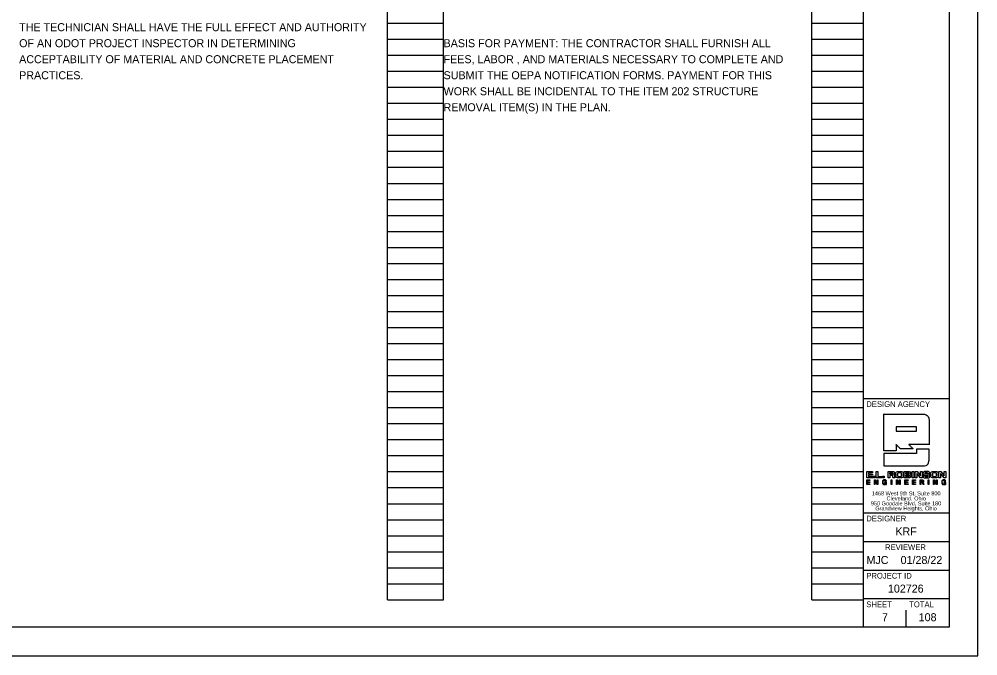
# Model space of a CAD drawing. Extents: x 0 to 34, y 0 to 22.
# Drawn here: x 17.24 to 34, y 0 to 11.13 of the extents above; entities that cross this region are included whole.
import ezdxf

# ---------------------------------------------------------------- set-up
doc = ezdxf.new("R2010")
doc.units = 0
for name, color, linetype in [('SH_Border', 7, 'Continuous'), ('SH_Cut_Line', 7, 'Continuous'), ('SH_Data', 7, 'Continuous'), ('SH_Text', 7, 'Continuous')]:
    doc.layers.add(name, color=color, linetype=linetype)

msp = doc.modelspace()

# ---------------------------------------------------------------- linework, layer by layer
at = {"layer": 'SH_Border'}
for p, q in [((32, 0.5), (32, 21.5)), ((32, 4.5), (33.5, 4.5)), ((32, 2.5), (33.5, 2.5)), ((32, 2), (33.5, 2)), ((32, 1.5), (33.5, 1.5)), ((32, 1), (33.5, 1))]:
    msp.add_line(p, q, dxfattribs=at)
msp.add_lwpolyline([(1.5, 21.5), (33.5, 21.5), (33.5, 0.5), (1.5, 0.5)], close=True, dxfattribs=at)
at = {"layer": 'SH_Cut_Line'}
msp.add_lwpolyline([(0, 0), (34, 0), (34, 22), (0, 22)], close=True, dxfattribs=at)
at = {"layer": 'SH_Data'}
for p, q in [((23.68, 0.98), (23.68, 21.14)), ((24.66, 0.98), (24.66, 21.14)), ((31.1, 0.98), (31.1, 21.14)), ((32, 0.98), (32, 21.14)), ((23.68, 11.06), (24.66, 11.06)), ((31.1, 11.06), (32, 11.06)), ((23.68, 10.78), (24.66, 10.78)), ((31.1, 10.78), (32, 10.78)), ((23.68, 10.5), (24.66, 10.5)), ((31.1, 10.5), (32, 10.5)), ((23.68, 10.22), (24.66, 10.22)), ((31.1, 10.22), (32, 10.22)), ((23.68, 9.94), (24.66, 9.94)), ((31.1, 9.94), (32, 9.94)), ((23.68, 9.66), (24.66, 9.66)), ((31.1, 9.66), (32, 9.66)), ((23.68, 9.38), (24.66, 9.38)), ((31.1, 9.38), (32, 9.38)), ((23.68, 9.1), (24.66, 9.1)), ((31.1, 9.1), (32, 9.1)), ((23.68, 8.82), (24.66, 8.82)), ((31.1, 8.82), (32, 8.82)), ((23.68, 8.54), (24.66, 8.54)), ((31.1, 8.54), (32, 8.54)), ((23.68, 8.26), (24.66, 8.26)), ((31.1, 8.26), (32, 8.26)), ((23.68, 7.98), (24.66, 7.98)), ((31.1, 7.98), (32, 7.98)), ((23.68, 7.7), (24.66, 7.7)), ((31.1, 7.7), (32, 7.7)), ((23.68, 7.42), (24.66, 7.42)), ((31.1, 7.42), (32, 7.42)), ((23.68, 7.14), (24.66, 7.14)), ((31.1, 7.14), (32, 7.14)), ((23.68, 6.86), (24.66, 6.86)), ((31.1, 6.86), (32, 6.86)), ((23.68, 6.58), (24.66, 6.58)), ((31.1, 6.58), (32, 6.58)), ((23.68, 6.3), (24.66, 6.3)), ((31.1, 6.3), (32, 6.3)), ((23.68, 6.02), (24.66, 6.02)), ((31.1, 6.02), (32, 6.02)), ((23.68, 5.74), (24.66, 5.74)), ((31.1, 5.74), (32, 5.74)), ((23.68, 5.46), (24.66, 5.46)), ((31.1, 5.46), (32, 5.46)), ((23.68, 5.18), (24.66, 5.18)), ((31.1, 5.18), (32, 5.18)), ((23.68, 4.9), (24.66, 4.9)), ((31.1, 4.9), (32, 4.9)), ((23.68, 4.62), (24.66, 4.62)), ((31.1, 4.62), (32, 4.62)), ((23.68, 4.34), (24.66, 4.34)), ((31.1, 4.34), (32, 4.34)), ((23.68, 4.06), (24.66, 4.06)), ((31.1, 4.06), (32, 4.06)), ((32.929, 4.003), (32.574, 4.003)), ((32.574, 4.003), (32.574, 3.925)), ((32.574, 3.925), (32.929, 3.925)), ((32.929, 3.925), (32.929, 4.003)), ((23.68, 3.78), (24.66, 3.78)), ((31.1, 3.78), (32, 3.78)), ((23.68, 3.5), (24.66, 3.5)), ((31.1, 3.5), (32, 3.5)), ((32.75, 3.5), (32.75, 3.5)), ((23.68, 3.22), (24.66, 3.22)), ((31.1, 3.22), (32, 3.22)), ((32.463, 3.201), (32.463, 3.173)), ((32.743, 3.202), (32.743, 3.178)), ((32.743, 3.159), (32.743, 3.133)), ((33.001, 3.066), (33.001, 3.039)), ((33.001, 3.039), (33.023, 3.039)), ((23.68, 2.94), (24.66, 2.94)), ((31.1, 2.94), (32, 2.94)), ((23.68, 2.66), (24.66, 2.66)), ((31.1, 2.66), (32, 2.66)), ((23.68, 2.38), (24.66, 2.38)), ((31.1, 2.38), (32, 2.38)), ((23.68, 2.1), (24.66, 2.1)), ((31.1, 2.1), (32, 2.1)), ((23.68, 1.82), (24.66, 1.82)), ((31.1, 1.82), (32, 1.82)), ((23.68, 1.54), (24.66, 1.54)), ((31.1, 1.54), (32, 1.54)), ((23.68, 1.26), (24.66, 1.26)), ((31.1, 1.26), (32, 1.26)), ((23.68, 0.98), (24.66, 0.98)), ((31.1, 0.98), (32, 0.98)), ((32.375, 0.675), (32.375, 0.675)), ((32.75, 0.5), (32.75, 0.8))]:
    msp.add_line(p, q, dxfattribs=at)
for points in [[(32.06, 3.221), (32.161, 3.221), (32.161, 3.201), (32.089, 3.201), (32.089, 3.178), (32.158, 3.178), (32.158, 3.158), (32.089, 3.158), (32.089, 3.133), (32.162, 3.133), (32.162, 3.113), (32.06, 3.113), (32.06, 3.221)], [(32.22, 3.221), (32.249, 3.221), (32.249, 3.134), (32.316, 3.134), (32.316, 3.113), (32.22, 3.113), (32.22, 3.221)], [(32.851, 3.221), (32.881, 3.221), (32.881, 3.113), (32.851, 3.113), (32.851, 3.221)], [(32.999, 3.221), (33.027, 3.221), (33.027, 3.113), (32.995, 3.113), (32.936, 3.189), (32.936, 3.189), (32.936, 3.113), (32.907, 3.113), (32.907, 3.221), (32.941, 3.221), (32.999, 3.146), (32.999, 3.146), (32.999, 3.221)], [(33.413, 3.221), (33.442, 3.221), (33.442, 3.113), (33.41, 3.113), (33.35, 3.189), (33.35, 3.189), (33.35, 3.113), (33.321, 3.113), (33.321, 3.221), (33.356, 3.221), (33.413, 3.146), (33.413, 3.146), (33.413, 3.221)], [(32.059, 3.075), (32.114, 3.075), (32.114, 3.066), (32.07, 3.066), (32.07, 3.041), (32.111, 3.041), (32.111, 3.032), (32.07, 3.032), (32.07, 3.005), (32.114, 3.005), (32.114, 2.996), (32.059, 2.996), (32.059, 3.075)], [(32.175, 3.139), (32.205, 3.139), (32.205, 3.113), (32.175, 3.113), (32.175, 3.139)], [(32.191, 3.075), (32.203, 3.075), (32.244, 3.011), (32.244, 3.011), (32.244, 3.075), (32.254, 3.075), (32.254, 2.996), (32.243, 2.996), (32.202, 3.059), (32.201, 3.059), (32.201, 2.996), (32.191, 2.996), (32.191, 3.075)], [(32.331, 3.139), (32.361, 3.139), (32.361, 3.113), (32.331, 3.113), (32.331, 3.139)], [(32.487, 3.075), (32.498, 3.075), (32.498, 2.996), (32.487, 2.996), (32.487, 3.075)], [(32.581, 3.075), (32.592, 3.075), (32.633, 3.011), (32.633, 3.011), (32.633, 3.075), (32.643, 3.075), (32.643, 2.996), (32.632, 2.996), (32.591, 3.059), (32.591, 3.059), (32.591, 2.996), (32.581, 2.996), (32.581, 3.075)], [(32.726, 3.075), (32.781, 3.075), (32.781, 3.066), (32.737, 3.066), (32.737, 3.041), (32.778, 3.041), (32.778, 3.032), (32.737, 3.032), (32.737, 3.005), (32.781, 3.005), (32.781, 2.996), (32.726, 2.996), (32.726, 3.075)], [(32.859, 3.075), (32.913, 3.075), (32.913, 3.066), (32.869, 3.066), (32.869, 3.041), (32.91, 3.041), (32.91, 3.032), (32.869, 3.032), (32.869, 3.005), (32.913, 3.005), (32.913, 2.996), (32.859, 2.996), (32.859, 3.075)], [(33.133, 3.075), (33.143, 3.075), (33.143, 2.996), (33.133, 2.996), (33.133, 3.075)], [(33.226, 3.075), (33.237, 3.075), (33.279, 3.011), (33.279, 3.011), (33.279, 3.075), (33.289, 3.075), (33.289, 2.996), (33.277, 2.996), (33.236, 3.059), (33.236, 3.059), (33.236, 2.996), (33.226, 2.996), (33.226, 3.075)]]:
    msp.add_lwpolyline(points, dxfattribs=at)
for points, degree in [([(32.356, 3.583), (32.356, 3.586), (32.356, 4.224), (32.356, 4.227)], 2), ([(32.356, 4.227), (32.36, 4.227), (33.03, 4.227), (33.034, 4.227), (33.096, 4.227), (33.147, 4.177), (33.147, 4.114)], 3), ([(33.147, 4.114), (33.147, 4.112), (33.147, 3.694), (33.147, 3.692)], 2), ([(32.645, 3.621), (32.645, 3.621), (32.574, 3.691), (32.574, 3.692)], 2), ([(32.574, 3.692), (32.574, 3.691), (32.574, 3.583), (32.574, 3.583)], 2), ([(33.147, 3.692), (33.145, 3.692), (32.795, 3.692), (32.793, 3.692)], 2), ([(32.793, 3.692), (32.793, 3.691), (32.866, 3.621), (32.866, 3.621)], 2), ([(32.929, 3.615), (32.929, 3.615), (33.147, 3.615), (33.147, 3.615), (33.147, 3.615), (33.147, 3.433), (33.147, 3.433), (33.147, 3.37), (33.096, 3.32), (33.034, 3.32), (33.034, 3.32), (32.356, 3.32), (32.356, 3.32), (32.356, 3.32), (32.356, 3.537), (32.356, 3.537), (32.356, 3.537), (32.929, 3.537), (32.929, 3.537), (32.929, 3.537), (32.929, 3.615), (32.929, 3.615)], 3), ([(32.574, 3.583), (32.573, 3.583), (32.357, 3.583), (32.356, 3.583)], 2), ([(32.866, 3.621), (32.865, 3.621), (32.646, 3.621), (32.645, 3.621)], 2), ([(32.433, 3.113), (32.433, 3.113), (32.433, 3.221), (32.433, 3.221)], 2), ([(32.433, 3.221), (32.433, 3.221), (32.512, 3.221), (32.512, 3.221), (32.542, 3.221), (32.545, 3.203), (32.546, 3.192)], 3), ([(32.463, 3.173), (32.463, 3.173), (32.502, 3.173), (32.502, 3.173), (32.508, 3.173), (32.516, 3.177), (32.516, 3.187), (32.516, 3.198), (32.507, 3.201), (32.5, 3.201), (32.5, 3.201), (32.463, 3.201), (32.463, 3.201), (32.463, 3.201), (32.463, 3.173), (32.463, 3.173)], 3), ([(32.463, 3.173), (32.476, 3.173), (32.489, 3.173), (32.508, 3.173), (32.516, 3.177), (32.516, 3.198), (32.507, 3.201), (32.488, 3.201), (32.475, 3.201), (32.463, 3.201)], 3), ([(32.546, 3.192), (32.544, 3.179), (32.542, 3.17), (32.53, 3.166)], 2), ([(32.631, 3.11), (32.573, 3.11), (32.567, 3.145), (32.565, 3.167), (32.564, 3.19), (32.573, 3.224), (32.631, 3.224)], 3), ([(32.631, 3.13), (32.658, 3.13), (32.667, 3.15), (32.667, 3.167), (32.667, 3.184), (32.658, 3.204), (32.631, 3.204), (32.604, 3.204), (32.595, 3.184), (32.595, 3.167), (32.595, 3.15), (32.604, 3.13), (32.631, 3.13)], 3), ([(32.631, 3.204), (32.604, 3.204), (32.595, 3.184), (32.595, 3.167), (32.595, 3.15), (32.604, 3.13), (32.631, 3.13)], 3), ([(32.631, 3.224), (32.69, 3.224), (32.695, 3.189), (32.697, 3.167), (32.699, 3.144), (32.69, 3.11), (32.631, 3.11)], 3), ([(32.631, 3.13), (32.658, 3.13), (32.667, 3.15), (32.667, 3.167), (32.667, 3.184), (32.658, 3.204), (32.631, 3.204)], 3), ([(32.714, 3.113), (32.714, 3.113), (32.714, 3.221), (32.714, 3.221)], 2), ([(32.714, 3.221), (32.714, 3.221), (32.795, 3.221), (32.795, 3.221)], 2), ([(32.743, 3.178), (32.743, 3.178), (32.784, 3.178), (32.784, 3.178), (32.791, 3.178), (32.796, 3.182), (32.796, 3.19), (32.796, 3.197), (32.793, 3.202), (32.78, 3.202), (32.78, 3.202), (32.743, 3.202), (32.743, 3.202), (32.743, 3.202), (32.743, 3.178), (32.743, 3.178)], 3), ([(32.743, 3.178), (32.757, 3.178), (32.771, 3.178), (32.791, 3.181), (32.791, 3.183), (32.792, 3.197), (32.793, 3.202), (32.768, 3.202), (32.756, 3.202), (32.743, 3.202)], 3), ([(32.795, 3.221), (32.81, 3.218), (32.826, 3.214), (32.826, 3.194)], 2), ([(32.826, 3.194), (32.824, 3.186), (32.822, 3.175), (32.812, 3.172)], 2), ([(33.126, 3.19), (33.124, 3.204), (33.111, 3.206), (33.099, 3.206), (33.087, 3.206), (33.079, 3.2), (33.079, 3.193), (33.079, 3.187), (33.084, 3.184), (33.091, 3.183), (33.091, 3.183), (33.128, 3.177), (33.128, 3.177), (33.148, 3.173), (33.163, 3.166), (33.163, 3.146), (33.163, 3.126), (33.149, 3.11), (33.107, 3.11), (33.08, 3.11), (33.046, 3.113), (33.045, 3.147), (33.045, 3.147), (33.079, 3.147), (33.079, 3.147), (33.079, 3.132), (33.094, 3.129), (33.107, 3.129), (33.121, 3.129), (33.13, 3.134), (33.13, 3.143), (33.13, 3.151), (33.123, 3.154), (33.112, 3.155), (33.112, 3.155), (33.085, 3.16), (33.085, 3.16), (33.066, 3.162), (33.047, 3.168), (33.047, 3.19), (33.047, 3.215), (33.067, 3.224), (33.101, 3.224), (33.124, 3.224), (33.157, 3.221), (33.159, 3.19), (33.159, 3.19), (33.126, 3.19), (33.126, 3.19)], 3), ([(33.242, 3.11), (33.183, 3.11), (33.178, 3.145), (33.176, 3.167), (33.174, 3.19), (33.183, 3.224), (33.242, 3.224)], 3), ([(33.242, 3.13), (33.269, 3.13), (33.278, 3.15), (33.278, 3.167), (33.278, 3.184), (33.269, 3.204), (33.242, 3.204), (33.215, 3.204), (33.205, 3.184), (33.205, 3.167), (33.205, 3.15), (33.215, 3.13), (33.242, 3.13)], 3), ([(33.242, 3.204), (33.215, 3.204), (33.205, 3.184), (33.205, 3.167), (33.205, 3.15), (33.215, 3.13), (33.242, 3.13)], 3), ([(33.242, 3.224), (33.3, 3.224), (33.306, 3.189), (33.308, 3.167), (33.309, 3.144), (33.3, 3.11), (33.242, 3.11)], 3), ([(33.242, 3.13), (33.269, 3.13), (33.278, 3.15), (33.278, 3.167), (33.278, 3.184), (33.269, 3.204), (33.242, 3.204)], 3), ([(32.396, 3.006), (32.39, 2.998), (32.38, 2.994), (32.37, 2.994), (32.347, 2.994), (32.333, 3.014), (32.333, 3.034), (32.333, 3.057), (32.346, 3.077), (32.37, 3.077), (32.388, 3.077), (32.401, 3.069), (32.404, 3.051), (32.404, 3.051), (32.394, 3.051), (32.394, 3.051), (32.392, 3.062), (32.382, 3.068), (32.37, 3.068), (32.351, 3.068), (32.344, 3.051), (32.344, 3.034), (32.344, 3.018), (32.353, 3.003), (32.37, 3.003), (32.387, 3.003), (32.396, 3.015), (32.396, 3.029), (32.396, 3.029), (32.371, 3.029), (32.371, 3.029), (32.371, 3.029), (32.371, 3.038), (32.371, 3.038), (32.371, 3.038), (32.405, 3.038), (32.405, 3.038), (32.405, 3.038), (32.405, 2.996), (32.405, 2.996), (32.405, 2.996), (32.398, 2.996), (32.398, 2.996), (32.398, 2.996), (32.396, 3.006), (32.396, 3.006)], 3), ([(32.463, 3.113), (32.462, 3.113), (32.433, 3.113), (32.433, 3.113)], 2), ([(32.499, 3.153), (32.499, 3.153), (32.463, 3.153), (32.463, 3.153)], 2), ([(32.463, 3.153), (32.463, 3.152), (32.463, 3.113), (32.463, 3.113)], 2), ([(32.518, 3.113), (32.516, 3.118), (32.516, 3.122), (32.516, 3.134), (32.515, 3.149), (32.508, 3.15), (32.499, 3.153)], 3), ([(32.55, 3.113), (32.55, 3.113), (32.518, 3.113), (32.518, 3.113)], 2), ([(32.53, 3.166), (32.53, 3.166), (32.53, 3.165), (32.53, 3.165)], 2), ([(32.53, 3.165), (32.543, 3.163), (32.544, 3.147), (32.544, 3.136)], 2), ([(32.544, 3.136), (32.544, 3.131), (32.548, 3.119), (32.55, 3.113)], 2), ([(32.829, 3.145), (32.827, 3.132), (32.824, 3.113), (32.791, 3.113), (32.791, 3.113), (32.714, 3.113), (32.714, 3.113)], 3), ([(32.743, 3.133), (32.743, 3.133), (32.787, 3.133), (32.787, 3.133), (32.796, 3.133), (32.8, 3.139), (32.8, 3.146), (32.8, 3.155), (32.794, 3.159), (32.784, 3.159), (32.784, 3.159), (32.743, 3.159), (32.743, 3.159), (32.743, 3.159), (32.743, 3.133), (32.743, 3.133)], 3), ([(32.743, 3.133), (32.758, 3.133), (32.772, 3.133), (32.796, 3.133), (32.8, 3.139), (32.8, 3.155), (32.794, 3.159), (32.77, 3.159), (32.757, 3.159), (32.743, 3.159)], 3), ([(32.812, 3.172), (32.812, 3.172), (32.812, 3.172), (32.812, 3.172)], 2), ([(32.812, 3.172), (32.824, 3.17), (32.827, 3.156), (32.829, 3.145)], 2), ([(32.991, 3.075), (32.991, 3.075), (33.027, 3.075), (33.028, 3.075), (33.042, 3.075), (33.051, 3.067), (33.051, 3.054)], 3), ([(32.991, 2.996), (32.991, 2.997), (32.991, 3.074), (32.991, 3.075)], 2), ([(33.023, 3.039), (33.033, 3.039), (33.041, 3.041), (33.041, 3.052), (33.041, 3.06), (33.037, 3.066), (33.027, 3.066), (33.027, 3.066), (33.001, 3.066), (33.001, 3.066), (33.001, 3.066), (33.001, 3.039), (33.001, 3.039), (33.001, 3.039), (33.023, 3.039), (33.023, 3.039)], 3), ([(33.023, 3.039), (33.033, 3.039), (33.041, 3.041), (33.041, 3.06), (33.037, 3.066), (33.018, 3.066), (33.01, 3.066), (33.001, 3.066)], 3), ([(33.04, 3.016), (33.038, 3.023), (33.037, 3.03), (33.027, 3.03), (33.027, 3.03), (33.001, 3.03), (33.001, 3.03)], 3), ([(33.001, 3.03), (33.001, 3.03), (33.001, 2.996), (33.001, 2.996)], 2), ([(33.051, 3.054), (33.049, 3.045), (33.047, 3.037), (33.038, 3.034)], 2), ([(33.038, 3.034), (33.038, 3.034), (33.038, 3.034), (33.038, 3.034)], 2), ([(33.038, 3.034), (33.044, 3.029), (33.047, 3.025), (33.048, 3.018)], 2), ([(33.048, 3.018), (33.049, 3.01), (33.052, 3.002), (33.054, 2.996)], 2), ([(33.43, 3.006), (33.424, 2.998), (33.414, 2.994), (33.405, 2.994), (33.382, 2.994), (33.368, 3.014), (33.368, 3.034), (33.368, 3.057), (33.38, 3.077), (33.405, 3.077), (33.422, 3.077), (33.436, 3.069), (33.439, 3.051), (33.439, 3.051), (33.429, 3.051), (33.429, 3.051), (33.426, 3.062), (33.417, 3.068), (33.405, 3.068), (33.386, 3.068), (33.378, 3.051), (33.378, 3.034), (33.378, 3.018), (33.388, 3.003), (33.405, 3.003), (33.421, 3.003), (33.431, 3.015), (33.43, 3.029), (33.43, 3.029), (33.405, 3.029), (33.405, 3.029), (33.405, 3.029), (33.405, 3.038), (33.405, 3.038), (33.405, 3.038), (33.44, 3.038), (33.44, 3.038), (33.44, 3.038), (33.44, 2.996), (33.44, 2.996), (33.44, 2.996), (33.433, 2.996), (33.433, 2.996), (33.433, 2.996), (33.43, 3.006), (33.43, 3.006)], 3), ([(33.001, 2.996), (33.001, 2.996), (32.991, 2.996), (32.991, 2.996)], 2), ([(33.043, 2.996), (33.042, 3), (33.041, 3.008), (33.04, 3.016)], 2), ([(33.054, 2.996), (33.054, 2.996), (33.043, 2.996), (33.043, 2.996)], 2)]:
    msp.add_open_spline(points, degree=degree, dxfattribs=at)

# ---------------------------------------------------------------- texts
for s, height, p in [('DESIGN AGENCY', 0.1, (32.05, 4.35)), ('1468 West 9th St, Suite 800', 0.07, (32.145, 2.805)), ('950 Goodale Blvd, Suite 180', 0.07, (32.13, 2.63)), ('Cleveland, Ohio', 0.07, (32.404, 2.717)), ('Grandview Heights, Ohio', 0.07, (32.208, 2.542)), ('DESIGNER', 0.1, (32.05, 2.35)), ('KRF', 0.14, (32.559, 2.105)), ('REVIEWER', 0.1, (32.378, 1.85)), ('MJC', 0.14, (32.053, 1.605)), ('01/28/22', 0.14, (32.65, 1.605)), ('PROJECT ID', 0.1, (32.05, 1.35)), ('102726', 0.14, (32.428, 1.105)), ('SHEET', 0.1, (32.05, 0.85)), ('TOTAL', 0.1, (32.8, 0.85)), ('7', 0.14, (32.325, 0.605)), ('108', 0.14, (32.966, 0.605))]:
    msp.add_text(s, height=height, dxfattribs=at).set_placement(p)
at = {"layer": 'SH_Text'}
for s, p in [('THE TECHNICIAN SHALL HAVE THE FULL EFFECT AND AUTHORITY ', (17.24, 10.92)), ('OF AN ODOT PROJECT INSPECTOR IN DETERMINING ', (17.24, 10.64)), ('BASIS FOR PAYMENT: THE CONTRACTOR SHALL FURNISH ALL ', (24.66, 10.64)), ('ACCEPTABILITY OF MATERIAL AND CONCRETE PLACEMENT ', (17.24, 10.36)), ('FEES, LABOR , AND MATERIALS NECESSARY TO COMPLETE AND ', (24.66, 10.36)), ('PRACTICES.', (17.24, 10.08)), ('SUBMIT THE OEPA NOTIFICATION FORMS. PAYMENT FOR THIS ', (24.66, 10.08)), ('WORK SHALL BE INCIDENTAL TO THE ITEM 202 STRUCTURE ', (24.66, 9.8)), ('REMOVAL ITEM(S) IN THE PLAN.', (24.66, 9.52))]:
    msp.add_text(s, height=0.14, dxfattribs=at).set_placement(p)

doc.saveas('drawing.dxf')
